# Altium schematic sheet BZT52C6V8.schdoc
size 127 x 101 mm
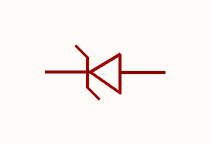
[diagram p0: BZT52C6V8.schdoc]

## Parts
ZD?  bzt52c6v8_c2120  [SOD-123_L2.8-W1.8-LS3.7-RD]  (value not drawn)

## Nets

Not connected (* = marked no-connect by the designer): ZD? 1(K) 2(A)

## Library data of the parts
ZD? = bzt52c6v8_c2120: 二极管配置:1个独立式;稳压值(标称值):6.8V;稳压值(范围值):6.4V~7.2V;耗散功率(Pd):500mW;; Manufacturer: CJ(江苏长电/长晶); AddInBom: yes; ModelId: 7884390a25fb4c08947731ebfba7e3f8; ModelTransform: 144.8816,62.992,0,0,0,0,0,0,0; Diode Configuration: 1个独立式; Zener Voltage(Nom): 6.8V; Reverse Leakage Current (Ir): 2uA; Pd - Power Dissipation: 500mW; Impedance(Zzt): 15Ω; Impedance(Zzk): 80Ω; Operating Junction Temperature Range: -55℃~+150℃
